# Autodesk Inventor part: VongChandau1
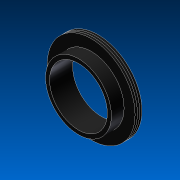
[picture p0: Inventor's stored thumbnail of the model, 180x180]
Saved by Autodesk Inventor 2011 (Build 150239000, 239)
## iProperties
Created: 2011-05
Part Number: VongChandau1
Document SubType Name: Modeling
Designer: 904Chiaki
Density: 1 g/cm^3
Author: 904Chiaki
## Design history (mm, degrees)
sketch "Sketch1"
  geometry: L1 (-67.896, 37.236)-(-67.896, -14.881); L2 (-42.896, 12.111)-(-42.896, -7.889); L3 (-42.896, 12.111)-(-39.396, 12.111); L4 (-39.396, -7.889)-(-42.896, -7.889); L5 (-39.396, 9.111)-(-29.896, 9.111); L6 (-29.896, 3.111)-(-39.396, 3.111); L7 (-29.896, 9.111)-(-31.628, 8.111); L8 (-31.628, 8.111)-(-29.896, 7.111); L9 (-29.896, 7.111)-(-31.628, 6.111); L10 (-31.628, 6.111)-(-29.896, 5.111); L11 (-29.896, 5.111)-(-31.628, 4.111); L12 (-31.628, 4.111)-(-29.896, 3.111); L13 (-39.396, 12.111)-(-39.396, 9.111); L14 (-39.396, 3.111)-(-39.396, -7.889); 1 further point
  constraints: 28 end point
  dimensions: "d0" = 20 distance of L2.start L2.end; "d1" = 3.5 distance of L2.start L3.end; "d2" = 25 distance between parallel lines of L2 L1; "d3" = 38 distance from line of L1 L5.end; "d4" = 3 distance between parallel lines of L3 L5; "d5" = 6 distance of L5.end L6.start; "d11" = 30 deg angle of L5 L7
revolve "Revolution1" sketch "Sketch1" stored, may be unused: angle "d12" = 90 deg
body "Solid1"
